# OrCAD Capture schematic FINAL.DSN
size A
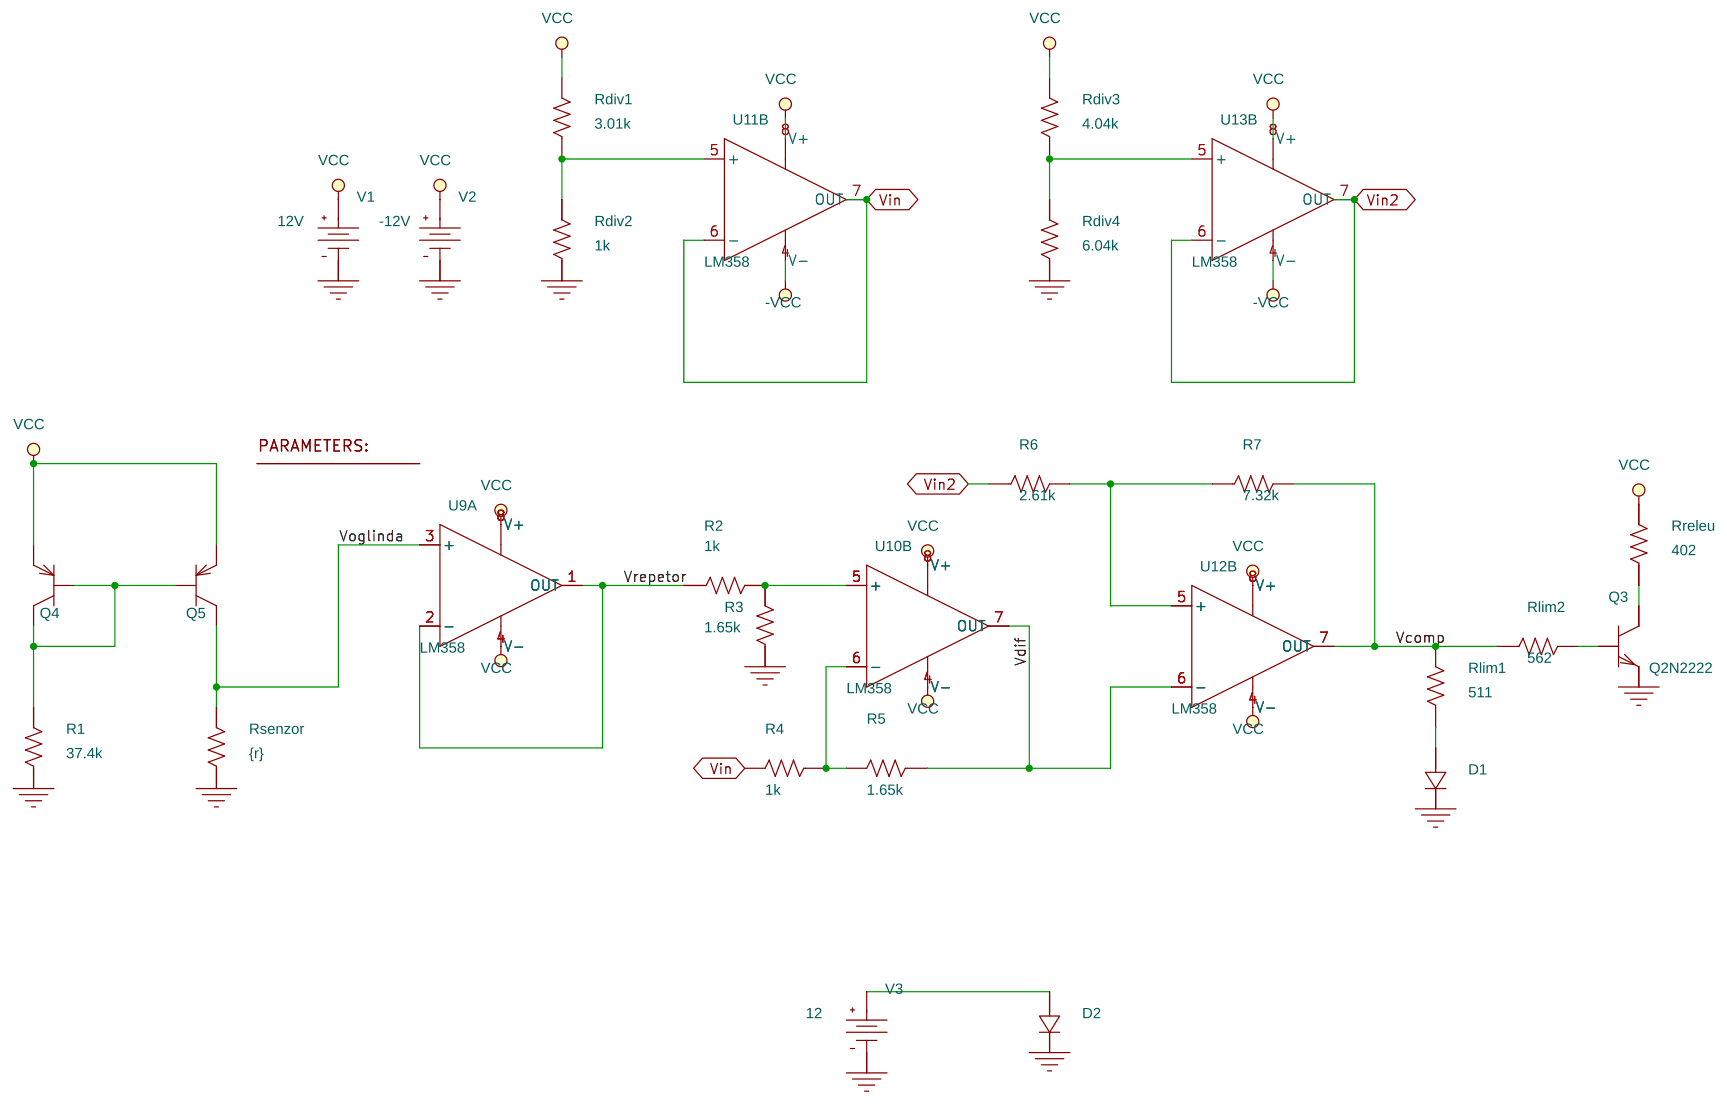
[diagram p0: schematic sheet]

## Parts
1  PARAM
2  PARAM
D1  Dbreak
D2  Dbreak
Q3  Q2N2222  [TO18]
Q4  Q2N6727/ZTX
Q5  Q2N6727/ZTX
R1  37.4k  [AXRC05]
R2  1k  [AXRC05]
R3  1.65k  [AXRC05]
R4  1k  [AXRC05]
R5  1.65k  [AXRC05]
R6  2.61k  [AXRC05]
R7  7.32k  [AXRC05]
Rdiv1  3.01k  [AXRC05]
Rdiv2  1k  [AXRC05]
Rdiv3  4.04k  [AXRC05]
Rdiv4  6.04k  [AXRC05]
Rlim1  511  [AXRC05]
Rlim2  562  [AXRC05]
Rreleu  402  [AXRC05]
Rsenzor  {r}  [AXRC05]
U9  LM358  [DIP1008W300L450]  (section A)
U10  LM358  [DIP1008W300L450]  (section B)
U11  LM358  [DIP1008W300L450]  (section B)
U12  LM358  [DIP1008W300L450]  (section B)
U13  LM358  [DIP1008W300L450]  (section B)
V1  12V
V2  VDC
V3  VDC

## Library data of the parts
1 = PARAM
2 = PARAM: r: 10k
D1 D2 = Dbreak
Q3 = Q2N2222
Q4 Q5 = Q2N6727_ZTX
R1-R7 Rdiv1-Rdiv4 Rlim1 Rlim2 Rreleu = R: TOLERANCE: 1%
Rsenzor = R: TOLERANCE: 20%
U9-U13 = LM358
V1 = VDC
V2 = VDC: DC: -12V
V3 = VDC: DC: 12

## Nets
-VCC: U9.4(V-) U10.4(V-) U11.4(V-) U12.4(V-) U13.4(V-) V2.0(+)
VCC: Q4.3(e) Q5.3(e) Rdiv1.2 Rdiv3.2 Rreleu.2 U9.8(V+) U10.8(V+) U11.8(V+) U12.8(V+) U13.8(V+) V1.0(+)
Vin: R4.2 U11.6(-) U11.7(OUT)
Vin2: R6.1 U13.6(-) U13.7(OUT)
0: D1.1(2) D2.1(2) Q3.1(e) R1.1 R3.1 Rdiv2.1 Rdiv4.1 Rsenzor.1 V1.1(-) V2.1(-) V3.1(-)
Vcomp: R7.2 Rlim1.2 Rlim2.1 U12.7(OUT)
Vdif: R5.1 U10.7(OUT) U12.6(-)
Voglinda: Q5.2(c) Rsenzor.2 U9.3(+)
Vrepetor: R2.1 U9.1(OUT) U9.2(-)
N22957: Q4.1(b) Q4.2(c) Q5.1(b) R1.2
N25899: R2.2 R3.2 U10.5(+)
N25943: R4.1 R5.2 U10.6(-)
N27409: Rdiv1.1 Rdiv2.2 U11.5(+)
N28500: Rdiv3.1 Rdiv4.2 U13.5(+)
N28775: R6.2 R7.1 U12.5(+)
N29523: Q3.3(c) Rreleu.1
N29591: Q3.2(b) Rlim2.2
N29627: D1.0(1) Rlim1.1
N35500: D2.0(1) V3.0(+)
